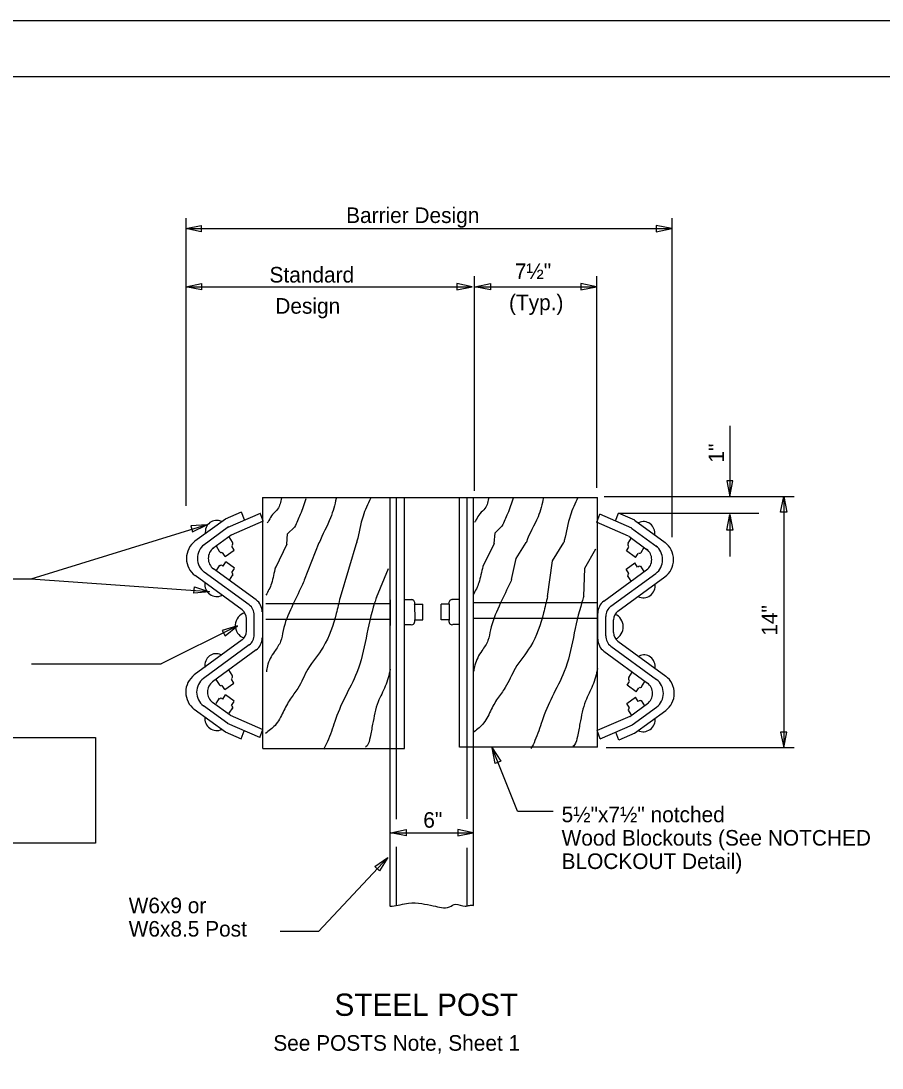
# Model space of a CAD drawing. Extents: x 0 to 34, y 0 to 22.
# Drawn here: x 11.64 to 19.37, y 12.6 to 22 of the extents above; entities that cross this region are included whole.
import ezdxf

# ---------------------------------------------------------------- set-up
doc = ezdxf.new("R2010")
doc.units = 0
for name, color, linetype in [('SH_Border', 7, 'Continuous'), ('SH_Cut_Line', 7, 'Continuous'), ('ST_Details', 7, 'Continuous'), ('ST_Text', 7, 'Continuous')]:
    doc.layers.add(name, color=color, linetype=linetype)

msp = doc.modelspace()

# ---------------------------------------------------------------- linework, layer by layer
at = {"layer": 'SH_Border'}
msp.add_lwpolyline([(1.5, 21.5), (33.5, 21.5), (33.5, 0.5), (1.5, 0.5)], close=True, dxfattribs=at)
at = {"layer": 'SH_Cut_Line'}
msp.add_lwpolyline([(0, 0), (34, 0), (34, 22), (0, 22)], close=True, dxfattribs=at)
at = {"layer": 'ST_Details'}
for p, q in [((13.8045, 17.7204), (16.8155, 17.7204)), ((13.8045, 17.7204), (13.8045, 15.4639)), ((14.9532, 15.4641), (14.9532, 17.7132)), ((15.0099, 15.4641), (15.0099, 17.7132)), ((15.0807, 15.4641), (15.0807, 17.7132)), ((15.5737, 15.4784), (15.5737, 17.7179)), ((15.6445, 15.4784), (15.6445, 17.7179)), ((15.7012, 15.4784), (15.7012, 17.7179)), ((16.8112, 17.7204), (16.8112, 15.4782)), ((13.4719, 17.5269), (13.6158, 17.5897)), ((13.6433, 17.5196), (13.6163, 17.5889)), ((13.4722, 17.5266), (13.1992, 17.3266)), ((13.4967, 17.4539), (13.7861, 17.5802)), ((13.5258, 17.3834), (13.8154, 17.5096)), ((13.8122, 17.5101), (13.7852, 17.5792)), ((17.0938, 17.3726), (16.8043, 17.4989)), ((16.8074, 17.4992), (16.8344, 17.5686)), ((17.1231, 17.4431), (16.8336, 17.5694)), ((16.9764, 17.5089), (17.0034, 17.5781)), ((17.1478, 17.5161), (17.0038, 17.5789)), ((17.1475, 17.5157), (17.4204, 17.3157)), ((13.4992, 17.4554), (13.2692, 17.2867)), ((14.0938, 17.4547), (14.0315, 17.3941)), ((15.8855, 17.3072), (15.8937, 17.4012)), ((15.9561, 17.4619), (15.8937, 17.4012)), ((17.1205, 17.4446), (17.3506, 17.2759)), ((13.525, 17.3829), (13.3583, 17.2607)), ((13.5364, 17.3182), (13.5062, 17.3656)), ((14.0233, 17.3001), (14.0315, 17.3941)), ((14.3129, 17.3119), (14.1808, 16.9761)), ((14.6532, 17.3251), (14.5026, 16.8231)), ((15.8855, 17.3072), (15.7845, 17.1011)), ((17.0891, 17.3096), (17.1192, 17.3569)), ((17.0947, 17.3721), (17.2614, 17.2499)), ((13.4207, 17.2357), (13.3915, 17.2814)), ((13.4693, 17.1892), (13.4462, 17.2256)), ((13.4692, 17.1897), (13.5517, 17.2482)), ((13.5516, 17.2482), (13.5289, 17.2837)), ((14.0233, 17.3001), (13.9212, 17.0892)), ((17.1563, 17.1811), (17.0737, 17.2397)), ((17.0738, 17.2396), (17.0965, 17.2751)), ((17.1561, 17.1807), (17.1792, 17.2169)), ((17.2048, 17.2271), (17.2339, 17.2727)), ((13.4509, 17.1034), (13.4756, 17.1421)), ((13.5541, 17.0844), (13.4754, 17.1419)), ((17.0714, 17.0757), (17.1501, 17.1332)), ((17.1745, 17.0947), (17.1498, 17.1334)), ((13.686, 16.7546), (13.2821, 17.0491)), ((13.7492, 16.7996), (13.3645, 17.0799)), ((13.391, 17.0631), (13.4227, 17.1131)), ((13.509, 16.9771), (13.54, 17.0256)), ((13.5299, 17.0459), (13.5537, 17.0834)), ((14.8283, 16.8231), (14.9367, 17.0819)), ((16.8705, 16.7889), (17.2552, 17.0692)), ((16.9337, 16.7439), (17.3376, 17.0382)), ((17.0956, 17.0372), (17.0717, 17.0749)), ((17.2345, 17.0544), (17.2027, 17.1044)), ((13.6228, 16.7096), (13.1997, 17.0181)), ((16.9969, 16.6989), (17.4201, 17.0072)), ((17.1164, 16.9684), (17.0855, 17.0171)), ((14.9487, 16.7654), (13.8367, 16.7654)), ((14.9547, 16.5689), (14.9547, 16.8014)), ((15.0792, 16.8028), (15.1477, 16.8028)), ((15.1715, 16.7619), (15.2442, 16.7619)), ((15.1715, 16.7619), (15.1725, 16.6218)), ((15.2442, 16.6218), (15.2442, 16.7619)), ((15.4088, 16.6218), (15.4088, 16.7609)), ((15.4816, 16.7619), (15.4098, 16.7619)), ((15.4816, 16.7619), (15.4805, 16.6218)), ((15.5737, 16.8028), (15.5054, 16.8028)), ((16.8109, 16.7724), (15.699, 16.7724)), ((13.732, 16.4887), (13.732, 16.6619)), ((16.8169, 16.4482), (16.8169, 16.6807)), ((16.8877, 16.4779), (16.8877, 16.6511)), ((13.6612, 16.5181), (13.6612, 16.6324)), ((13.732, 16.5699), (13.732, 16.5807)), ((14.9487, 16.6253), (13.8364, 16.6253)), ((15.0792, 16.5783), (15.1388, 16.5783)), ((15.1725, 16.6218), (15.2442, 16.6218)), ((15.4805, 16.6218), (15.4088, 16.6218)), ((15.5737, 16.5783), (15.5142, 16.5783)), ((16.8109, 16.6323), (15.6986, 16.6323)), ((16.8877, 16.5592), (16.8877, 16.5699)), ((16.9585, 16.5072), (16.9585, 16.6217)), ((13.623, 16.4409), (13.1927, 16.1256)), ((13.6862, 16.3962), (13.2751, 16.0947)), ((16.9335, 16.3854), (17.3446, 16.0839)), ((16.9967, 16.4302), (17.4271, 16.1147)), ((13.7495, 16.3512), (13.3577, 16.0641)), ((16.8702, 16.3404), (17.262, 16.0532)), ((13.4182, 16.0409), (13.3892, 16.0866)), ((13.5341, 16.1236), (13.5039, 16.1709)), ((13.5492, 16.0534), (13.5266, 16.0889)), ((17.0947, 16.1031), (17.1248, 16.1504)), ((13.467, 15.9946), (13.4438, 16.0309)), ((13.4668, 15.9949), (13.5493, 16.0536)), ((17.162, 15.9744), (17.0794, 16.0331)), ((17.0795, 16.0329), (17.1022, 16.0684)), ((17.1617, 15.9741), (17.1849, 16.0104)), ((17.2105, 16.0204), (17.2396, 16.0661)), ((13.3886, 15.8684), (13.4203, 15.9184)), ((13.4486, 15.9087), (13.4732, 15.9474)), ((13.5517, 15.8897), (13.473, 15.9472)), ((17.0771, 15.8692), (17.1557, 15.9267)), ((17.1802, 15.8882), (17.1555, 15.9269)), ((17.2402, 15.8479), (17.2084, 15.8979)), ((13.4725, 15.6132), (13.193, 15.8169)), ((13.4932, 15.6892), (13.2755, 15.8479)), ((13.5153, 15.7642), (13.3579, 15.8789)), ((13.5067, 15.7822), (13.5377, 15.8309)), ((13.5275, 15.8512), (13.5514, 15.8887)), ((17.1012, 15.8307), (17.0773, 15.8682)), ((17.1221, 15.7617), (17.0912, 15.8104)), ((17.1043, 15.7534), (17.2617, 15.8681)), ((17.1264, 15.6784), (17.3442, 15.8371)), ((17.1472, 15.6024), (17.4267, 15.8061)), ((13.5153, 15.7646), (13.8091, 15.6366)), ((17.1043, 15.7537), (16.8107, 15.6257)), ((13.4702, 15.6141), (13.6142, 15.5512)), ((13.7811, 15.5634), (13.4917, 15.6897)), ((13.6132, 15.5516), (13.6416, 15.6242)), ((13.7802, 15.5634), (13.809, 15.6371)), ((16.8394, 15.5526), (16.8107, 15.6262)), ((16.8386, 15.5526), (17.1281, 15.6789)), ((17.0064, 15.5409), (16.9781, 15.6134)), ((17.1495, 15.6032), (17.0056, 15.5406)), ((13.8095, 15.4641), (15.0807, 15.4641)), ((14.9532, 14.0519), (14.9532, 15.4641)), ((15.0099, 14.8304), (15.0099, 15.4641)), ((16.8155, 15.4784), (15.5737, 15.4784)), ((15.6445, 14.8326), (15.6445, 15.4784)), ((15.7012, 14.0566), (15.7012, 15.4784)), ((15.0099, 14.0519), (15.0099, 14.5829)), ((15.6445, 14.0566), (15.6445, 14.5742))]:
    msp.add_line(p, q, dxfattribs=at)
for points in [[(16.043, 16.9832), (16.0821, 17.1722), (16.1742, 17.3162)], [(16.3647, 16.8301), (16.4097, 17.1497), (16.5112, 17.3162)], [(16.6906, 16.8301), (16.701, 17.0854), (16.799, 17.2589)]]:
    msp.add_lwpolyline(points, dxfattribs=at)
for centre, major_axis, start_param, end_param in [((13.3919, 17.4076), (0, -0.1065), 2.687211, 4.851441), ((17.2278, 17.3968), (0, -0.1065), 1.431744, 3.595974), ((13.3001, 17.1724), (0, -0.1875), 3.747084, 5.680264), ((13.5205, 17.3058), (0, 0.0198), 3.70437, 5.352473), ((17.1049, 17.2972), (0, 0.0198), 0.930712, 2.578815), ((17.3196, 17.1616), (0, -0.1875), 0.602921, 2.536101), ((13.3624, 17.1725), (0, -0.15), 3.747137, 5.680324), ((13.4248, 17.1726), (0, -0.1125), 3.747102, 5.680297), ((13.4335, 17.2463), (0, -0.0195), 5.247458, 6.879592), ((17.192, 17.2377), (0, -0.0195), 5.686779, 7.318912), ((17.1949, 17.1618), (0, -0.1125), 0.602888, 2.536083), ((17.2573, 17.1617), (0, -0.15), 0.602861, 2.536048), ((13.4352, 17.0899), (0, 0.021), 5.452301, 7.118326), ((13.5208, 17.0274), (0, 0.021), 4.196406, 5.73538), ((17.1046, 17.0188), (0, 0.021), 0.547805, 2.086779), ((17.1903, 17.0813), (0, 0.021), 5.448045, 7.11407), ((13.3951, 16.9451), (0, -0.115), 4.640651, 6.714317), ((17.2246, 16.9343), (0, -0.115), 5.852054, 7.925719), ((13.6257, 16.662), (0, 0.1125), 4.712389, 5.68034), ((13.6789, 16.6916), (0, 0.1312), 4.712389, 5.680267), ((15.146, 16.7733), (0, -0.0298), 2.729343, 3.43401), ((15.1449, 16.7725), (0, 0.03), 4.35702, 6.237266), ((15.146, 16.7733), (0, -0.0298), 1.431351, 1.439211), ((15.5081, 16.7725), (0, 0.03), 0.045919, 1.926166), ((15.507, 16.7733), (0, -0.0298), 4.843974, 4.851834), ((15.507, 16.7733), (0, -0.0298), 2.849176, 3.553842), ((16.9408, 16.6808), (0, 0.1312), 0.602918, 1.570796), ((16.994, 16.6512), (0, 0.1125), 0.602846, 1.570796), ((13.6719, 16.5699), (0, -0.1171), 3.363241, 5.976631), ((13.5726, 16.6324), (0, 0.0937), 4.712389, 5.680377), ((17.0471, 16.6216), (0, 0.0937), 0.602808, 1.570796), ((16.9331, 16.5587), (0, -0.1192), 0.40519, 2.779828), ((15.1438, 16.6101), (0, -0.0326), 6.093782, 8.224205), ((15.5092, 16.6101), (0, -0.0326), 4.342165, 6.472589), ((13.5726, 16.5181), (0, -0.0937), 0.605563, 1.570796), ((13.6257, 16.4886), (0, -0.1125), 0.605651, 1.570796), ((13.6789, 16.4591), (0, -0.1312), 0.605566, 1.570796), ((16.994, 16.4778), (0, -0.1125), 4.712389, 5.677535), ((17.0471, 16.5073), (0, -0.0937), 4.712389, 5.677623), ((16.9408, 16.4483), (0, -0.1312), 4.712389, 5.677619), ((13.3888, 16.2107), (0, -0.1065), 2.687211, 4.851441), ((17.2309, 16.1999), (0, -0.1065), 1.431744, 3.595974), ((13.2934, 15.9714), (0, -0.1875), 3.747091, 5.68028), ((13.3558, 15.9715), (0, -0.15), 3.747115, 5.680355), ((13.5182, 16.1111), (0, 0.0198), 3.70437, 5.352473), ((17.1106, 16.0906), (0, 0.0198), 0.930712, 2.578815), ((17.264, 15.9607), (0, -0.15), 0.602831, 2.53607), ((17.3263, 15.9606), (0, -0.1875), 0.602905, 2.536094), ((13.4182, 15.9716), (0, -0.1125), 3.747102, 5.680258), ((13.4311, 16.0516), (0, -0.0195), 5.247458, 6.879592), ((17.1976, 16.0311), (0, -0.0195), 5.686779, 7.318912), ((17.2015, 15.9608), (0, -0.1125), 0.602927, 2.536083), ((13.4328, 15.8952), (0, 0.021), 5.452301, 7.118326), ((17.196, 15.8747), (0, 0.021), 5.448045, 7.11407), ((13.5185, 15.8327), (0, 0.021), 4.196406, 5.73538), ((17.1103, 15.8122), (0, 0.021), 0.547805, 2.086779), ((13.3951, 15.7418), (0, -0.115), 4.640651, 6.714317), ((17.2246, 15.731), (0, -0.115), 5.852054, 7.925719)]:
    msp.add_ellipse(centre, major_axis=major_axis, ratio=0.944544, start_param=start_param, end_param=end_param, dxfattribs=at)
for points in [[(13.977, 17.7161), (13.9407, 17.6152), (13.8952, 17.5671), (13.8635, 17.5142), (13.8472, 17.4884)], [(14.195, 17.7066), (14.145, 17.5671), (14.0938, 17.4547)], [(14.4674, 17.7114), (14.4175, 17.5382), (14.3131, 17.3122), (14.3119, 17.3091)], [(14.7762, 17.7114), (14.7081, 17.5527), (14.6536, 17.3267), (14.6489, 17.3091)], [(15.8392, 17.7232), (15.8029, 17.6224), (15.7574, 17.5742), (15.7257, 17.5214), (15.7095, 17.4956)], [(16.0572, 17.7137), (16.0072, 17.5742), (15.9561, 17.4619)], [(16.3297, 17.7186), (16.2797, 17.5454), (16.1752, 17.3194), (16.1742, 17.3162)], [(16.6384, 17.7186), (16.5703, 17.5599), (16.5158, 17.3339), (16.5112, 17.3162)], [(13.9223, 17.0939), (13.9044, 17.0191), (13.8862, 16.9469), (13.8362, 16.8412)], [(15.7845, 17.1011), (15.7666, 17.0262), (15.7484, 16.9541), (15.6984, 16.8482)], [(14.1808, 16.9761), (14.1587, 16.9277), (14.0677, 16.7354), (13.9907, 16.5239), (13.968, 16.4277), (13.9135, 16.3364), (13.8499, 16.2067), (13.8407, 16.1537)], [(16.043, 16.9832), (16.0208, 16.9349), (15.93, 16.7426), (15.8528, 16.5311), (15.8302, 16.4349), (15.7757, 16.3436), (15.7121, 16.2137), (15.703, 16.1609)], [(14.5026, 16.8231), (14.4674, 16.6777), (14.3494, 16.3749), (14.2132, 16.1777), (14.1222, 16.0047), (14.0542, 15.9086), (13.9907, 15.7932), (13.918, 15.6731), (13.8317, 15.6009)], [(14.8283, 16.8231), (14.8125, 16.7739), (14.7352, 16.4566), (14.6536, 16.1489), (14.5446, 15.9231), (14.4537, 15.7066), (14.3902, 15.5287), (14.3539, 15.4567)], [(16.3647, 16.8301), (16.3297, 16.6849), (16.2116, 16.3821), (16.0753, 16.1849), (15.9845, 16.0119), (15.9164, 15.9157), (15.8528, 15.8004), (15.7802, 15.6802), (15.6939, 15.6081)], [(16.6906, 16.8301), (16.6747, 16.7811), (16.5975, 16.4637), (16.5158, 16.1561), (16.4068, 15.9302), (16.316, 15.7137), (16.2524, 15.5359), (16.2162, 15.4639)], [(14.9532, 16.1777), (14.9079, 16.0241), (14.8442, 15.8846), (14.7944, 15.6826), (14.7717, 15.5672), (14.7444, 15.4902), (14.7307, 15.4759)], [(16.8155, 16.1849), (16.7702, 16.0311), (16.7065, 15.8917), (16.6566, 15.6897), (16.6338, 15.5744), (16.6067, 15.4974), (16.593, 15.4831)], [(14.9503, 14.0496), (14.969, 14.0502), (15.1172, 14.0771), (15.2352, 14.0722), (15.3397, 14.0531), (15.485, 14.0434), (15.5395, 14.0674), (15.6258, 14.0482), (15.6657, 14.0566), (15.7012, 14.0566)]]:
    msp.add_spline(points, degree=3, dxfattribs=at)
at = {"layer": 'ST_Text'}
for p, q in [((13.1181, 20.2294), (13.1182, 17.6452)), ((17.4818, 20.2294), (17.4818, 17.3636)), ((13.1161, 20.1349), (17.4818, 20.1349)), ((15.7064, 19.7074), (15.7064, 17.7811)), ((16.8052, 19.7074), (16.8052, 17.8052)), ((13.1177, 19.6129), (13.6959, 19.6129)), ((13.6959, 19.6129), (15.6893, 19.6129)), ((15.7121, 19.6129), (16.0798, 19.6129)), ((16.0798, 19.6129), (16.8052, 19.6129)), ((18.0021, 18.3635), (18.0021, 17.7281)), ((16.8747, 17.7281), (18.5807, 17.7281)), ((18.4862, 17.7281), (18.4862, 17.0224)), ((17.0038, 17.5789), (18.2621, 17.5789)), ((18.0021, 17.5662), (18.0021, 17.1912)), ((13.3303, 16.8739), (11.7236, 16.9862)), ((18.4862, 17.0224), (18.4862, 15.4734)), ((13.5814, 16.5672), (12.8962, 16.2255)), ((11.7312, 16.2255), (12.8962, 16.2255)), ((16.0947, 14.9026), (15.8677, 15.4704)), ((16.8926, 15.4734), (18.5807, 15.4734)), ((16.0947, 14.9026), (16.4156, 14.9026)), ((14.9532, 14.7091), (15.6984, 14.7091)), ((14.9569, 14.7091), (15.1444, 14.7091)), ((14.3082, 13.8227), (14.9325, 14.4876)), ((14.3082, 13.8227), (13.9654, 13.8227))]:
    msp.add_line(p, q, dxfattribs=at)
for points in [[(13.2561, 20.1069), (13.1161, 20.1349), (13.2561, 20.1629)], [(17.3418, 20.1069), (17.4818, 20.1349), (17.3418, 20.1629)], [(13.2577, 19.5849), (13.1177, 19.6129), (13.2577, 19.6409)], [(15.5493, 19.5849), (15.6893, 19.6129), (15.5493, 19.6409)], [(15.8521, 19.5849), (15.7121, 19.6129), (15.8521, 19.6409)], [(16.6652, 19.5849), (16.8052, 19.6129), (16.6652, 19.6409)], [(17.9741, 17.8681), (18.0021, 17.7281), (18.0301, 17.8681)], [(18.4582, 17.5881), (18.4862, 17.7281), (18.5142, 17.5881)], [(17.9741, 17.4262), (18.0021, 17.5662), (18.0301, 17.4262)], [(13.1775, 17.4101), (13.3044, 17.4756), (13.1621, 17.4639)], [(13.194, 16.9164), (13.3303, 16.8739), (13.1881, 16.8607)], [(13.471, 16.4768), (13.5814, 16.5672), (13.4447, 16.5262)], [(18.4582, 15.6134), (18.4862, 15.4734), (18.5142, 15.6134)], [(9.5197, 15.5651), (12.3046, 15.5651), (12.3046, 14.6162), (9.5197, 14.6162)], [(15.8942, 15.3301), (15.8677, 15.4704), (15.9461, 15.3511)], [(15.0969, 14.6811), (14.9569, 14.7091), (15.0969, 14.7371)], [(15.5584, 14.6811), (15.6984, 14.7091), (15.5584, 14.7371)], [(14.8151, 14.4063), (14.9325, 14.4876), (14.8554, 14.3674)]]:
    msp.add_lwpolyline(points, close=True, dxfattribs=at)
msp.add_lwpolyline([(13.3044, 17.4756), (11.7236, 16.9862), (11.4729, 16.9862)], dxfattribs=at)

# ---------------------------------------------------------------- texts
for s, height, p in [('Barrier Design', 0.14, (14.5566, 20.1851)), ('Standard', 0.14, (13.8685, 19.6506)), (' 7½"', 0.14, (16.0193, 19.6816)), (' Design', 0.14, (13.8685, 19.3706)), ('(Typ.)', 0.14, (16.0193, 19.4016)), ('6" ', 0.14, (15.2495, 14.7539)), ('5½"x7½" notched', 0.14, (16.4917, 14.8031)), ('Wood Blockouts (See NOTCHED', 0.14, (16.4917, 14.5931)), ('BLOCKOUT Detail)', 0.14, (16.4917, 14.3831)), ('W6x9 or', 0.14, (12.6039, 13.9858)), ('W6x8.5 Post', 0.14, (12.6039, 13.7758)), ('STEEL POST', 0.2, (14.4517, 13.0641)), ('See POSTS Note, Sheet 1', 0.14, (13.9025, 12.7508))]:
    msp.add_text(s, height=height, dxfattribs=at).set_placement(p)
for s, p in [('1" ', (17.951, 18.0337)), ('14" ', (18.4287, 16.4783))]:
    msp.add_text(s, height=0.14, rotation=90, dxfattribs=at).set_placement(p)

doc.saveas('drawing.dxf')
